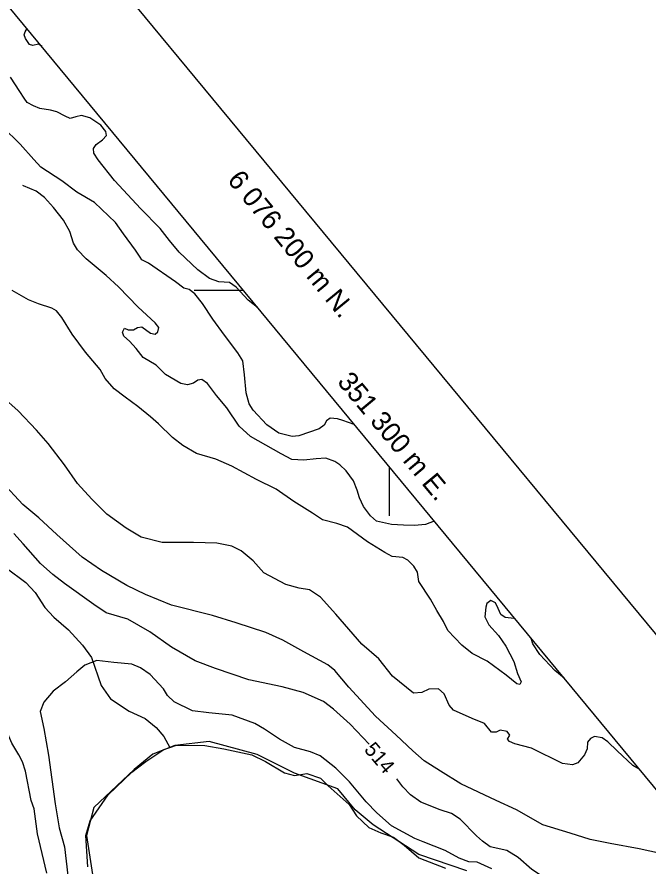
# Model space of a CAD drawing. Extents: x 347059 to 352153, y 6073752 to 6078601.
# Drawn here: x 351186.7 to 351378.9, y 6076024.5 to 6076283.3 of the extents above; entities that cross this region are included whole.
import ezdxf

# ---------------------------------------------------------------- set-up
doc = ezdxf.new("R2010")
doc.units = 0
for name, color, linetype in [('Level 1', 7, 'Continuous'), ('Level 2', 7, 'Continuous'), ('Level 4', 7, 'Continuous'), ('Level 44', 7, 'Continuous'), ('Level 60', 7, 'Continuous'), ('Level 61', 7, 'Continuous')]:
    doc.layers.add(name, color=color, linetype=linetype)

msp = doc.modelspace()

# ---------------------------------------------------------------- linework, layer by layer
at = {"layer": 'Level 1'}
for points in [[(351338.4, 6076099.82), (351338.13, 6076099.97), (351335.34, 6076100.25), (351334.04, 6076101.15), (351333.24, 6076103.01), (351332.43, 6076104.74), (351331.04, 6076105.42), (351329.75, 6076104.58), (351329.52, 6076103.44), (351329.23, 6076100.5), (351330.42, 6076098.02), (351333.35, 6076094.76), (351335.56, 6076091.56), (351338.02, 6076086.82), (351339.12, 6076083.2), (351340.23, 6076080.65), (351339.87, 6076079.81), (351338.96, 6076080.1), (351335.69, 6076082.66), (351329.88, 6076086.93), (351325.29, 6076089.3), (351322.17, 6076091.85), (351317.95, 6076096.29), (351316.57, 6076099), (351314.59, 6076102.4), (351312.68, 6076105.87), (351309.12, 6076111.27), (351308.68, 6076114.12), (351307.58, 6076115.87), (351305.7, 6076117.75), (351304.18, 6076118.59), (351300.96, 6076118.9), (351298.73, 6076120.08), (351293.42, 6076123.31), (351287.4, 6076127.81), (351284.09, 6076128.86), (351279.7, 6076130.06), (351276.67, 6076132.02), (351271.02, 6076135.64), (351265.67, 6076139.37), (351259.61, 6076142.36), (351252.12, 6076146.4), (351247.22, 6076148.51), (351241.35, 6076150.19), (351237.2, 6076152.67), (351234.05, 6076155.08), (351229.75, 6076159.31), (351227.3, 6076161.38), (351223.49, 6076164.57), (351219.59, 6076167.39), (351216.31, 6076169.96), (351213.51, 6076173.07), (351211.98, 6076175.79), (351207.53, 6076181.12), (351203.47, 6076186.64), (351200.37, 6076191.65), (351198.72, 6076193.73), (351197.26, 6076194.49), (351193.17, 6076195.82), (351190.22, 6076197.06), (351185.23, 6076199.9)], [(351353.32, 6076081.76), (351350.51, 6076084.14), (351345.97, 6076088.97), (351343.83, 6076092.24), (351343.32, 6076093.86)]]:
    msp.add_lwpolyline(points, dxfattribs=at)
at = {"layer": 'Level 2'}
for points in [[(351189.15, 6076278.7), (351189.72, 6076279.74)], [(351194.29, 6076274.21), (351193.18, 6076274.94), (351191.5, 6076274.56), (351190.44, 6076274.86), (351189.29, 6076276.67), (351188.87, 6076277.78), (351189.15, 6076278.7)], [(351212.72, 6076245.83), (351213.9, 6076247.11), (351213.77, 6076248.34), (351212.26, 6076250.26), (351208.84, 6076252.53), (351206.37, 6076253.23), (351204.55, 6076252.87), (351202.85, 6076252.35), (351201.32, 6076253.04), (351198.83, 6076254.39), (351196.85, 6076254.83), (351193.58, 6076255.37), (351191.7, 6076256.16), (351189.76, 6076257.17), (351188.85, 6076258.54), (351187.5, 6076260.59), (351184.73, 6076264.9)], [(351289.41, 6076159.1), (351285.9, 6076160.28), (351284.29, 6076160.77), (351282.07, 6076161.01), (351280.93, 6076160.16), (351280.26, 6076158.91), (351278.73, 6076157.73), (351272.53, 6076155.61), (351270.5, 6076155.47), (351266.47, 6076156.43), (351262.78, 6076159.02), (351258.58, 6076163.45), (351257.43, 6076165.41), (351256.45, 6076168.73), (351256, 6076174.24), (351255.45, 6076178.46), (351253.98, 6076180.95), (351249.92, 6076186.31), (351246.32, 6076191.13), (351243.23, 6076195.98), (351240.86, 6076198.9), (351239.08, 6076200.19), (351237.53, 6076200.6), (351234.94, 6076202.52), (351226.72, 6076208.2), (351224.71, 6076209.29), (351224.19, 6076210.05), (351222.77, 6076212.18), (351219.11, 6076217.22), (351216.63, 6076220.58), (351210.25, 6076226.77), (351204.86, 6076229.92), (351200.29, 6076233.37), (351193.9, 6076237.54), (351191.77, 6076239.87), (351187.65, 6076244.51), (351182.21, 6076249.76)], [(351259.94, 6076194.76), (351257.09, 6076196.94), (351253.43, 6076200.89), (351251.38, 6076202.34), (351248.16, 6076202.51), (351245.36, 6076203.59), (351241.75, 6076206.24), (351236.11, 6076211.57), (351233.15, 6076215.18), (351230.33, 6076218.78), (351224.31, 6076224.86), (351220.45, 6076229.04), (351216.4, 6076233.45), (351211.4, 6076239.74), (351210.04, 6076241.79), (351209.93, 6076243.16), (351210.74, 6076244.4), (351212.72, 6076245.83)], [(351219.45, 6076188.4), (351220.5, 6076187.96), (351222.15, 6076187.91), (351223.43, 6076188.61), (351224.75, 6076188.79), (351227.34, 6076186.86), (351228.77, 6076186.61), (351229.54, 6076187.27), (351229.86, 6076188.62), (351228.74, 6076190.08), (351223.54, 6076194.88), (351217.58, 6076201.04), (351213.87, 6076204.43), (351207.76, 6076209.52), (351205.15, 6076212.25), (351203.86, 6076214.37), (351202.75, 6076217.85), (351200.85, 6076221.32), (351197.82, 6076225.16), (351195.02, 6076228.27), (351192.56, 6076230.19), (351188.64, 6076231.79), (351188.43, 6076231.94)], [(351313.77, 6076129.62), (351311.08, 6076128.65), (351307.81, 6076128.25), (351304.43, 6076128.43), (351300.78, 6076128.64), (351296.17, 6076129.64), (351294.34, 6076131.29), (351292.18, 6076134.13), (351291.01, 6076136.74), (351290.32, 6076139.1), (351289.23, 6076141.93), (351286.93, 6076144.92), (351285.06, 6076146.79), (351283.54, 6076147.78), (351280.74, 6076148.86), (351277.84, 6076148.64), (351274.06, 6076148.21), (351270.4, 6076148.41), (351267.14, 6076150.18), (351257.8, 6076155.44), (351254.36, 6076158.52), (351250.6, 6076164.15), (351247.49, 6076167.92), (351244.66, 6076171.53), (351243.02, 6076172.81), (351241.71, 6076172.62), (351240.49, 6076171.7), (351238.65, 6076171.19), (351236.58, 6076171.57), (351231.95, 6076174.3), (351229.07, 6076177.2), (351225.06, 6076179.53), (351223.02, 6076182.21), (351220.96, 6076184.46), (351219.2, 6076186.04), (351218.85, 6076187.22), (351219.45, 6076188.4)], [(351318.35, 6076073.58), (351316.8, 6076076.96), (351315.04, 6076078.54), (351312.14, 6076078.47), (351309.97, 6076077.4), (351307.42, 6076077.23), (351301.09, 6076082.42), (351296.86, 6076087.66), (351291.69, 6076092.11), (351283.85, 6076101.25), (351279.1, 6076106.46), (351275.8, 6076108.74), (351272.58, 6076109.2), (351268.54, 6076110.3), (351261.86, 6076113.85), (351258.59, 6076117.5), (351254.99, 6076120.6), (351252.13, 6076122.05), (351247.5, 6076122.91), (351240.49, 6076123.07), (351230.87, 6076123.15), (351224.54, 6076124.72), (351219.9, 6076127.46), (351214.07, 6076131.74), (351209.42, 6076136.37), (351205.07, 6076141.12), (351201.15, 6076146.79), (351196.13, 6076153.26), (351192.6, 6076157.37), (351187.03, 6076163.23), (351182.28, 6076167.5)], [(351253.39, 6076098.68), (351246.24, 6076100.89), (351233.72, 6076104.01), (351225.77, 6076107.3), (351220.1, 6076109.98), (351212.39, 6076114.56), (351206.54, 6076118.7), (351198.78, 6076125.53), (351193.29, 6076130.67), (351188.45, 6076134.74), (351182, 6076141.62)], [(351294, 6076061.64), (351293.98, 6076061.67), (351288.2, 6076067.78), (351283.09, 6076072.3), (351280.01, 6076074.64), (351273.83, 6076077.43), (351267.5, 6076079.15), (351257.29, 6076081.3), (351247.16, 6076084.75), (351240.95, 6076087.11), (351233.78, 6076091.21), (351227.17, 6076095.93), (351220.48, 6076099.77), (351213.8, 6076101.73), (351210.07, 6076104.2), (351201.18, 6076110.61), (351197.6, 6076113.36), (351193.79, 6076116.7), (351188.5, 6076122.7), (351185.68, 6076125.82)], [(351195.77, 6076022.31), (351194.34, 6076028.31), (351192.91, 6076034.32), (351191.95, 6076041.93), (351191.03, 6076044.47), (351189.21, 6076053.46), (351188.31, 6076056.32), (351187.19, 6076058.37), (351185.06, 6076061.99), (351183.58, 6076065.55), (351182.19, 6076068.29), (351181.03, 6076070.02), (351180.18, 6076071.4), (351178.41, 6076073.52), (351176.99, 6076075.93), (351176.6, 6076077.11), (351175.58, 6076082.27), (351176.51, 6076085.48), (351176.5, 6076089.08), (351175.66, 6076092.6), (351174.38, 6076098.44), (351174.35, 6076103.77)], [(351382.68, 6076028.39), (351376.21, 6076029.82), (351367.36, 6076031.35), (351361.3, 6076032.6), (351355.16, 6076034.58), (351346.81, 6076037.09), (351338.84, 6076041.68), (351332.68, 6076044.47), (351321.84, 6076049.56), (351315.69, 6076053.43), (351310.71, 6076056.56), (351307.25, 6076059.65), (351302.18, 6076064.46), (351295.88, 6076070.23), (351287.78, 6076079.04), (351283.53, 6076084.15), (351281.41, 6076085.83), (351274.1, 6076089.79), (351267.63, 6076093.4), (351262.44, 6076095.68), (351253.39, 6076098.68)], [(351331.33, 6076023.73), (351326.83, 6076025.67), (351324.3, 6076025.78), (351321.41, 6076026.95), (351317.08, 6076029.31), (351310.38, 6076031.92), (351307.91, 6076032.9), (351300.79, 6076036.79), (351296.3, 6076040.76), (351292.99, 6076044.14), (351287.92, 6076050.2), (351283.8, 6076054.37), (351279, 6076058.08), (351276.04, 6076059.32), (351271.2, 6076060.7), (351266.66, 6076063.15), (351262.1, 6076066.26), (351259.17, 6076067.94), (351252.24, 6076070.5), (351245.1, 6076071.25), (351240.12, 6076071.85), (351234.51, 6076074.6), (351232.47, 6076076.5), (351231.31, 6076078.48), (351227.21, 6076082.94), (351224.3, 6076084.91), (351221.7, 6076086.05), (351216.13, 6076086.54), (351211.02, 6076087.15), (351207.34, 6076085.75), (351204.87, 6076083.75)], [(351204.87, 6076083.75), (351201.43, 6076080.66), (351197.65, 6076077.81), (351194.85, 6076074.45), (351193.76, 6076071.62), (351194.83, 6076066.43), (351196.26, 6076058.31), (351198.34, 6076043.44), (351199.47, 6076036.14), (351201.14, 6076030.4), (351202.11, 6076021.65)], [(351376.23, 6076054.04), (351374.32, 6076055.18), (351369.53, 6076059.67), (351366.63, 6076062.42), (351364.91, 6076063.64), (351362.56, 6076064.03), (351361.36, 6076063.4), (351360.48, 6076062.23), (351360.41, 6076060.28), (351359.55, 6076058.46), (351357.55, 6076055.94), (351355.92, 6076055.33), (351352.85, 6076055.78), (351343.45, 6076060.47), (351338.28, 6076061.8), (351336.74, 6076062.5), (351336.14, 6076063.19), (351336.81, 6076064.45), (351336.03, 6076065.52), (351333.89, 6076065.97), (351332.69, 6076065.33), (351331.24, 6076065.3), (351329.06, 6076068), (351325.35, 6076069.51), (351319.68, 6076072.03), (351318.35, 6076073.58)], [(351309.69, 6076044), (351306.53, 6076046.27), (351304.17, 6076048.7), (351302.37, 6076051.07)], [(351394.98, 6076006.41), (351394.56, 6076006.7), (351390.72, 6076008.51), (351386.33, 6076009.86), (351378.78, 6076012.53), (351374.27, 6076013.23), (351367.78, 6076013.57), (351361.34, 6076014.63), (351356.95, 6076015.03), (351354.16, 6076015.46), (351352.36, 6076016.61), (351348.57, 6076020.09), (351343.46, 6076023.52), (351339.31, 6076027.1), (351335.85, 6076029.25), (351330.86, 6076030.35), (351328.52, 6076032.12), (351326.69, 6076033.78), (351321.7, 6076038.81), (351319, 6076040.54), (351315.61, 6076041.66), (351309.69, 6076044)]]:
    msp.add_lwpolyline(points, dxfattribs=at)
at = {"layer": 'Level 4'}
for points in [[(351183.32, 6076115.41), (351189.37, 6076110.94), (351192.18, 6076107.89), (351195.2, 6076103.29), (351197.93, 6076100.33), (351202.37, 6076096.46), (351206.66, 6076091.87), (351209.35, 6076088.04), (351212.31, 6076079.51), (351215.15, 6076075.5), (351220.82, 6076071.69), (351225.7, 6076069.47), (351229.11, 6076066.77), (351231.41, 6076063.97), (351233.25, 6076060.66)], [(351208.24, 6076024.26), (351207.59, 6076033.88), (351208.92, 6076038.28), (351214.47, 6076046.18), (351221.64, 6076053.11), (351225.88, 6076056.42), (351231.38, 6076060.01), (351233.25, 6076060.66), (351235.23, 6076061.34), (351243.92, 6076061.31), (351249.65, 6076060.25), (351258.25, 6076058.42), (351262.42, 6076056.43), (351268.15, 6076052.9), (351271.17, 6076052.13), (351274.98, 6076052.68), (351279.12, 6076051.27), (351281.43, 6076049), (351287.84, 6076043.28), (351290.11, 6076039.86), (351293.87, 6076036.27), (351297.46, 6076034.63), (351301.37, 6076033.32), (351304.59, 6076030.85), (351309.11, 6076027.06), (351317.23, 6076023.89)]]:
    msp.add_lwpolyline(points, dxfattribs=at)
at = {"layer": 'Level 44'}
msp.add_lwpolyline([(351323.66, 6076023.05), (351309.08, 6076028.09), (351295.14, 6076037.09), (351289.73, 6076041.7), (351284.41, 6076048.02), (351271.19, 6076052.85), (351259.83, 6076058.5), (351245.21, 6076062.49), (351234.73, 6076061.25), (351228.03, 6076058.67), (351222.34, 6076053.94), (351210.03, 6076042.36), (351207.89, 6076033.86), (351210.33, 6076017.96)], dxfattribs=at)
at = {"layer": 'Level 60'}
for p, q in [((351240.61, 6076200), (351255.61, 6076200)), ((351300, 6076146.28), (351300, 6076131.28))]:
    msp.add_line(p, q, dxfattribs=at)
for points in [[(349811.7, 6077991.51), (350486.88, 6078550.39), (352105.73, 6076594.68), (351430.55, 6076035.79)], [(347109.95, 6075761.81), (348728.53, 6073803.05), (351407.22, 6076016.53), (349788.63, 6077975.29)]]:
    msp.add_lwpolyline(points, close=True, dxfattribs=at)

# ---------------------------------------------------------------- texts
at = {"layer": 'Level 2'}
msp.add_text('514', height=4.5, rotation=310.4202, dxfattribs=at).set_placement((351292.19, 6076059.89))
at = {"layer": 'Level 61'}
for s, rotation, p in [('6 076 200 m N.', 309.3644, (351250.5, 6076233.46)), ('351 300 m E. ', 309.813, (351283.98, 6076171.97))]:
    msp.add_text(s, height=6.0001, rotation=rotation, dxfattribs=at).set_placement(p)

doc.saveas('drawing.dxf')
